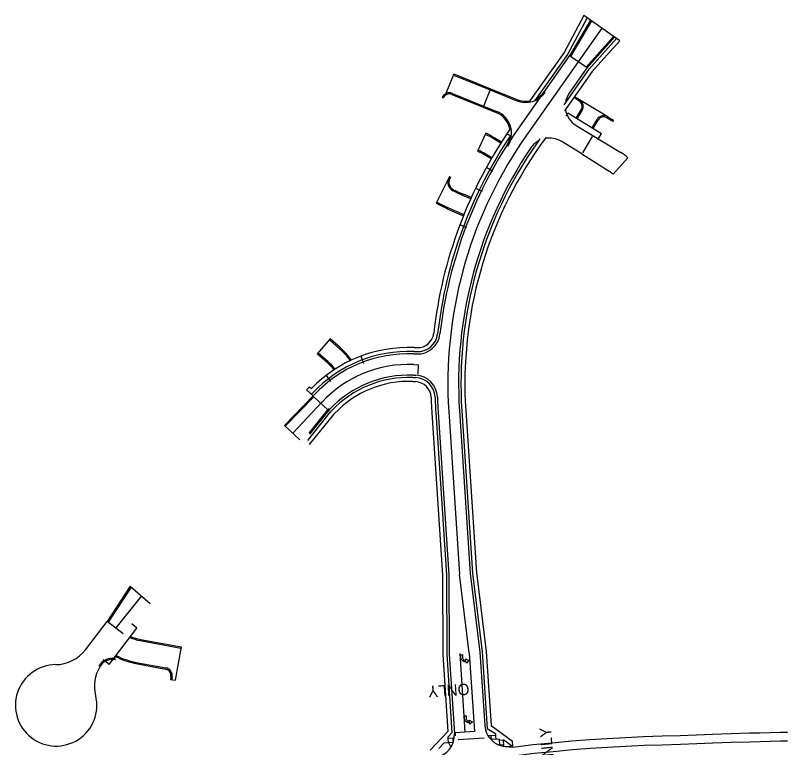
# Model space of a CAD drawing. Extents: x 979036 to 996074, y 1836928 to 1845163.
# Drawn here: x 982075 to 983051, y 1842691 to 1843617 of the extents above; entities that cross this region are included whole.
import ezdxf

# ---------------------------------------------------------------- set-up
doc = ezdxf.new("R2010")
doc.units = 0
for name, color, linetype in [('R_Proposed Road', 7, 'Continuous'), ('STRIPE_White Crosswalk', 7, 'Continuous'), ('STRIPE_White Stopbar', 7, 'Continuous'), ('STRIPE_White Turn Arrow', 7, 'Continuous'), ('STRIPE_WHITE_10_30 SKIP', 7, 'Continuous'), ('STRIPE_White_6in', 7, 'Continuous'), ('STRIPE_White_ONLY', 7, 'Continuous'), ('STRIPE_Yellow Dbl 6in', 7, 'Continuous')]:
    doc.layers.add(name, color=color, linetype=linetype)

msp = doc.modelspace()

# ---------------------------------------------------------------- linework, layer by layer
at = {"layer": 'R_Proposed Road'}
for p, q in [((982793.35, 1843617.45), (982768.45, 1843570.72)), ((982797.47, 1843614.55), (982772.72, 1843568.09)), ((982801.97, 1843611.38), (982775.24, 1843566.46)), ((982803.2, 1843610.52), (982776.53, 1843565.7)), ((982831, 1843590.94), (982796.16, 1843551.88)), ((982832.23, 1843590.08), (982797.28, 1843550.88)), ((982834.7, 1843588.34), (982799.51, 1843548.88)), ((982838.82, 1843585.44), (982803.25, 1843545.56)), ((982775.31, 1843566.56), (982709.93, 1843473.7)), ((982768.45, 1843570.72), (982724.01, 1843507.6)), ((982772.72, 1843568.09), (982731.61, 1843509.71)), ((982799.84, 1843549.29), (982768.31, 1843504.51)), ((982803.92, 1843546.41), (982768.89, 1843496.64)), ((982797.38, 1843551.02), (982774.95, 1843519.16)), ((982629.12, 1843543.47), (982618.97, 1843518.53)), ((982628.56, 1843542.08), (982674.87, 1843523.23)), ((982629.12, 1843543.47), (982675.44, 1843524.62)), ((982675.44, 1843524.62), (982666.01, 1843501.47)), ((982675.44, 1843524.62), (982709.11, 1843510.91)), ((982626.68, 1843517.47), (982666.01, 1843501.47)), ((982627.24, 1843518.86), (982666.58, 1843502.85)), ((982674.87, 1843523.23), (982708.55, 1843509.52)), ((982787.9, 1843510.82), (982781.56, 1843514.65)), ((982614.32, 1843513.64), (982615.7, 1843513.03)), ((982787.12, 1843509.53), (982780.69, 1843513.42)), ((982823.84, 1843489.09), (982787.9, 1843510.82)), ((982666.01, 1843501.47), (982682.71, 1843494.67)), ((982666.58, 1843502.85), (982683.28, 1843496.06)), ((982783.77, 1843487.56), (982790, 1843497.86)), ((982785.05, 1843486.78), (982791.28, 1843497.09)), ((982770.9, 1843490.43), (982773.07, 1843494.02)), ((982773.07, 1843494.02), (982815.86, 1843468.16)), ((982803.88, 1843475.4), (982810.11, 1843485.71)), ((982823.06, 1843487.81), (982830.17, 1843483.51)), ((982823.84, 1843489.09), (982830.95, 1843484.8)), ((982783.52, 1843478.36), (982839.97, 1843444.24)), ((982805.17, 1843474.62), (982811.39, 1843484.93)), ((982830.95, 1843484.8), (982830.17, 1843483.51)), ((982669.27, 1843468.5), (982658.86, 1843445.77)), ((982701.71, 1843464.3), (982696.1, 1843467.71)), ((982810.95, 1843460.03), (982815.86, 1843468.16)), ((982688.45, 1843455.98), (982680.16, 1843461.03)), ((982689.25, 1843457.25), (982680.94, 1843462.31)), ((982737.95, 1843461.39), (982734.46, 1843456.43)), ((982745.58, 1843463.55), (982738.55, 1843453.55)), ((982790.91, 1843442.34), (982764.6, 1843458.24)), ((982676.26, 1843435.89), (982667.94, 1843440.95)), ((982677.01, 1843437.19), (982668.72, 1843442.23)), ((982790.88, 1843442.36), (982825.46, 1843420.3)), ((982849.17, 1843437.48), (982830.63, 1843416.5)), ((982678.24, 1843420.05), (982670.11, 1843425)), ((982623.5, 1843413.67), (982606.8, 1843379.88)), ((982623.5, 1843413.67), (982624.85, 1843413.01)), ((982624.85, 1843413.01), (982623.88, 1843411.05)), ((982665.09, 1843394.57), (982656.36, 1843398.32)), ((982650.42, 1843385.63), (982640.59, 1843389.85)), ((982651.04, 1843387), (982641.18, 1843391.23)), ((982606.8, 1843379.88), (982616.11, 1843375.28)), ((982607.46, 1843381.23), (982616.78, 1843376.62)), ((982631.32, 1843368.26), (982641.18, 1843364.03)), ((982631.91, 1843369.64), (982641.74, 1843365.42)), ((982645.37, 1843348.62), (982636.63, 1843352.38)), ((982472.6, 1843208.29), (982456.1, 1843189.51)), ((982484.58, 1843195.77), (982471.61, 1843207.17)), ((982485.57, 1843196.9), (982472.6, 1843208.29)), ((982578.95, 1843197.3), (982582.34, 1843197.16)), ((982469.07, 1843178.12), (982456.1, 1843189.51)), ((982470.06, 1843179.24), (982457.09, 1843190.64)), ((982511.4, 1843186.39), (982514.75, 1843177.5)), ((982578.62, 1843189.3), (982582.02, 1843189.17)), ((982578.75, 1843192.3), (982582.14, 1843192.16)), ((982467.39, 1843161.87), (982473.18, 1843154.34)), ((982577.2, 1843154.33), (982580.59, 1843154.19)), ((982577.4, 1843159.33), (982580.79, 1843159.19)), ((982577.52, 1843162.33), (982580.92, 1843162.19)), ((982442.78, 1843143.78), (982446.6, 1843147.71)), ((982446.6, 1843147.71), (982448.94, 1843145.43)), ((982414.84, 1843098.76), (982451.09, 1843136.06)), ((982415.92, 1843097.71), (982452.16, 1843135.01)), ((982448.88, 1843138.08), (982450.34, 1843139.65)), ((982451.07, 1843136.04), (982452.53, 1843137.6)), ((982444.2, 1843079.57), (982473.21, 1843115.81)), ((982445.88, 1843088.87), (982469.69, 1843118.62)), ((982446.98, 1843087.84), (982470.87, 1843117.68)), ((982469.69, 1843118.62), (982471.16, 1843120.19)), ((982470.79, 1843117.6), (982472.25, 1843119.16)), ((982472.98, 1843115.55), (982474.45, 1843117.11)), ((982601.18, 1843114.85), (982614.59, 1842909.44)), ((982606.17, 1843115.17), (982619.59, 1842909.62)), ((982609.17, 1843115.37), (982622.59, 1842909.72)), ((982636.11, 1843117.13), (982649.53, 1842911.48)), ((982639.1, 1843117.32), (982652.52, 1842911.77)), ((982644.09, 1843117.65), (982657.5, 1842912.24)), ((982446.66, 1843074.64), (982477.11, 1843112.68)), ((982476.63, 1843112.13), (982478.1, 1843113.7)), ((982614.59, 1842909.73), (982615.12, 1842808.98)), ((982619.59, 1842909.75), (982620.12, 1842809.31)), ((982622.59, 1842909.77), (982623.12, 1842809.5)), ((982649.53, 1842911.53), (982662.04, 1842812.04)), ((982652.5, 1842911.9), (982665.04, 1842812.24)), ((982657.47, 1842912.53), (982670.04, 1842812.56)), ((982219.82, 1842895.34), (982190.77, 1842850.8)), ((982220.97, 1842894.35), (982191.96, 1842849.89)), ((982219.82, 1842895.34), (982245.08, 1842873.59)), ((982163.29, 1842815.06), (982190.77, 1842850.8)), ((982210.99, 1842835.26), (982190.77, 1842850.8)), ((982193.15, 1842796.47), (982228.22, 1842842.09)), ((982228.22, 1842842.09), (982221.99, 1842847.63)), ((982232.45, 1842826.58), (982283.98, 1842816.98)), ((982232.73, 1842828.05), (982284.25, 1842818.46)), ((982284.25, 1842818.46), (982276.43, 1842776.47)), ((982662.04, 1842812.04), (982668.1, 1842719.24)), ((982665.03, 1842812.24), (982671.35, 1842715.48)), ((982670.02, 1842812.56), (982676.13, 1842718.94)), ((982193.15, 1842796.47), (982185.62, 1842802.26)), ((982200.64, 1842802.39), (982200.92, 1842803.86)), ((982615.14, 1842808.98), (982621.5, 1842711.53)), ((982620.13, 1842809.31), (982626.63, 1842709.65)), ((982623.12, 1842809.5), (982629.69, 1842708.93)), ((982184.69, 1842798.6), (982186.81, 1842801.35)), ((982227.05, 1842797.58), (982264.5, 1842790.6)), ((982227.33, 1842799.05), (982264.78, 1842792.08)), ((982271.3, 1842780.69), (982270.72, 1842777.53)), ((982270.72, 1842777.53), (982276.43, 1842776.47)), ((982272.78, 1842780.42), (982272.19, 1842777.26)), ((982671.35, 1842715.48), (982681.61, 1842709.1)), ((982676.13, 1842718.94), (982703.09, 1842699.52)), ((982621.5, 1842711.53), (982599.06, 1842688.03)), ((982626.63, 1842709.65), (982621.86, 1842704.7)), ((982621.99, 1842702.7), (982621.86, 1842704.7)), ((982675.78, 1842706.21), (982676.11, 1842701.22)), ((982681.61, 1842709.1), (982681.77, 1842706.6)), ((982681.77, 1842706.6), (982682.1, 1842701.61)), ((982616.91, 1842697.36), (982610.13, 1842690.24)), ((982616.91, 1842697.36), (982628.3, 1842698.1)), ((982622.31, 1842697.71), (982621.99, 1842702.7)), ((982622.31, 1842697.71), (982625.37, 1842691.9)), ((982628.3, 1842698.1), (982627.98, 1842703.09)), ((982684.27, 1842701.76), (982682.1, 1842701.61)), ((982686.27, 1842701.89), (982686.76, 1842694.33)), ((982691.36, 1842700.64), (982686.32, 1842700.31)), ((982691.75, 1842694.65), (982686.76, 1842694.33)), ((982692.86, 1842700.74), (982691.36, 1842700.64)), ((982691.36, 1842700.64), (982691.86, 1842692.98)), ((982692.86, 1842700.74), (982703.33, 1842693.2)), ((982703.81, 1842693.24), (982703.09, 1842699.52)), ((982703.81, 1842693.24), (982699.73, 1842692.78)), ((982703.97, 1842691.75), (982699.9, 1842691.29))]:
    msp.add_line(p, q, dxfattribs=at)
for points in [[(982838.82, 1843585.44), (982793.35, 1843617.45)], [(982796.16, 1843551.88), (982776.53, 1843565.7)], [(982804.1, 1843464.17), (982791.69, 1843443.63)], [(982442.79, 1843143.78), (982451.07, 1843136.04)], [(982452.16, 1843135.01), (982469.69, 1843118.62)], [(982414.82, 1843098.73), (982434.18, 1843080.64)], [(982681.77, 1842706.6), (982672.37, 1842705.99)], [(982629.48, 1842703.19), (982621.99, 1842702.7)], [(982686.27, 1842701.89), (982676.11, 1842701.22)]]:
    msp.add_lwpolyline(points, dxfattribs=at)
for centre, radius, start, end in [((982623.47, 1843509.6), 10, 67.85265, 156.19028), ((982623.47, 1843509.6), 8.5, 67.85265, 156.19028), ((982719.86, 1843537.31), 30, 247.85265, 324.85265), ((982719.86, 1843537.31), 28.5, 298.3273, 324.85265), ((982798.26, 1843502.75), 28.5, 144.85265, 171.378), ((982719.86, 1843537.31), 28.5, 247.85265, 280.84922), ((982782.72, 1843502.26), 8.5, 328.85265, 58.85265), ((982782.72, 1843502.26), 10, 328.85265, 58.85265), ((982671.97, 1843468.27), 30, 327.41714, 67.85265), ((982798.26, 1843502.75), 28.5, 188.85608, 238.85265), ((982671.97, 1843468.27), 28.5, 10.44679, 67.85265), ((982818.67, 1843480.53), 10, 58.85265, 148.85265), ((982818.67, 1843480.53), 8.5, 58.85265, 148.85265), ((983167.15, 1843151.8), 567.17, 145.24329, 173.56683), ((983167.15, 1843151.8), 562.17, 145.84176, 173.56683), ((983167.15, 1843151.8), 559.17, 144.85265, 173.56683), ((982622.45, 1843366.2), 111, 58.67814, 65.40991), ((982622.45, 1843366.2), 112.5, 58.67814, 65.40991), ((983167.15, 1843151.8), 529.17, 144.85265, 183.73532), ((982671.97, 1843468.27), 28.5, 327.41714, 353.31514), ((982749.86, 1843433.85), 28.5, 118.74182, 145.94429), ((982749.86, 1843433.85), 28.5, 58.85265, 101.1144), ((983167.15, 1843151.8), 532.17, 145.94429, 183.73532), ((983167.15, 1843151.8), 524.17, 144.85265, 183.73532), ((982622.45, 1843366.2), 89, 58.67814, 65.40991), ((982622.45, 1843366.2), 87.5, 58.67814, 65.40991), ((982807.13, 1843389.9), 63.5, 48.53941, 58.85265), ((982807.13, 1843389.9), 35.5, 48.53941, 58.85265), ((982633.29, 1843406.39), 12, 153.6922, 244.02443), ((982633.29, 1843406.39), 10.5, 153.6922, 244.02443), ((982754.61, 1843655.41), 289, 244.02443, 246.76304), ((982754.61, 1843655.41), 287.5, 244.02443, 246.76304), ((982754.61, 1843655.41), 312.5, 243.6922, 246.76304), ((982754.61, 1843655.41), 311, 243.6922, 246.76304), ((982583.18, 1843217.64), 28.5, 267.66515, 353.56683), ((982583.18, 1843217.64), 25.5, 267.66515, 353.56683), ((982583.18, 1843217.64), 20.5, 267.66515, 353.56683), ((982571.96, 1843025.94), 171.5, 87.66515, 135.83424), ((982424.53, 1843127.4), 91, 35.91844, 48.7117), ((982424.53, 1843127.4), 92.5, 35.74275, 48.7117), ((982571.96, 1843025.94), 166.5, 87.66515, 136.92515), ((982571.96, 1843025.94), 163.5, 87.66515, 136.92515), ((982424.53, 1843127.4), 67.5, 38.19444, 48.7117), ((982424.53, 1843127.4), 69, 38.08422, 48.7117), ((982571.96, 1843025.94), 136.5, 87.66515, 136.92515), ((982571.96, 1843025.94), 133.5, 87.66515, 136.92515), ((982571.96, 1843025.94), 128.5, 87.66515, 136.92515), ((982579.76, 1843133.71), 20.5, 1.76347, 87.66515), ((982579.76, 1843133.71), 25.5, 1.76347, 87.66515), ((982579.76, 1843133.71), 28.5, 1.76347, 87.66515), ((983167.15, 1843151.8), 567.17, 181.76347, 183.73532), ((983167.15, 1843151.8), 562.17, 181.76347, 183.73532), ((983167.15, 1843151.8), 559.17, 181.76347, 183.73532), ((982244.54, 1842891.46), 64.5, 247.87466, 259.4497), ((982244.54, 1842891.46), 66, 247.51555, 259.4497), ((982124.84, 1842844.62), 48.5, 270.7606, 322.44446), ((982197.26, 1842784.2), 20, 79.4497, 149.64322), ((982197.26, 1842784.2), 18.5, 79.4497, 149.64322), ((982244.54, 1842891.46), 95.5, 242.79662, 259.4497), ((982244.54, 1842891.46), 94, 242.96368, 259.4497), ((982126.17, 1842744.63), 51.5, 90.7606, 14.12833), ((982223.14, 1842769.04), 48.5, 149.64322, 194.12833), ((982223.14, 1842769.04), 48.5, 142.44446, 149.64322), ((982262.95, 1842782.25), 8.5, 349.4497, 79.4497), ((982262.95, 1842782.25), 10, 349.4497, 79.4497), ((982696.54, 1842721.1), 28.5, 183.73532, 276.43492), ((982601.25, 1842707.07), 28.5, 279.12753, 3.73532)]:
    msp.add_arc(centre, radius, start, end, dxfattribs=at)
at = {"layer": 'STRIPE_White Crosswalk'}
msp.add_lwpolyline([(982667.21, 1842703.15), (982634.3, 1842701)], dxfattribs=at)
at = {"layer": 'STRIPE_White Stopbar'}
msp.add_line((982583.98, 1843163.56), (982584.46, 1843175.55), dxfattribs=at)
msp.add_lwpolyline([(982655.08, 1842711.37), (982631.13, 1842709.81)], dxfattribs=at)
at = {"layer": 'STRIPE_White Turn Arrow'}
for points in [[(982644.04, 1842803.28), (982647.88, 1842801.21), (982644.89, 1842798.03), (982644.62, 1842799.67), (982643.96, 1842799.62), (982643.38, 1842799.62), (982642.57, 1842799.74), (982641.61, 1842800.04), (982640.85, 1842800.41), (982640.22, 1842800.92), (982639.49, 1842801.5), (982639.05, 1842802.16), (982638.57, 1842802.87), (982638.24, 1842803.8), (982638.03, 1842804.77), (982637.84, 1842808.66), (982639.84, 1842808.77), (982640.05, 1842805.18), (982640.14, 1842804.49), (982640.41, 1842803.78), (982640.83, 1842803.02), (982641.44, 1842802.42), (982641.76, 1842802.22), (982642.4, 1842801.89), (982643.17, 1842801.69), (982643.91, 1842801.63), (982644.3, 1842801.64)], [(982648.59, 1842726.06), (982652.43, 1842723.98), (982649.45, 1842720.8), (982649.18, 1842722.44), (982648.52, 1842722.4), (982647.94, 1842722.4), (982647.13, 1842722.51), (982646.17, 1842722.81), (982645.41, 1842723.18), (982644.78, 1842723.69), (982644.05, 1842724.27), (982643.61, 1842724.93), (982643.13, 1842725.65), (982642.8, 1842726.57), (982642.58, 1842727.54), (982642.39, 1842731.44), (982644.4, 1842731.54), (982644.6, 1842727.95), (982644.7, 1842727.27), (982644.96, 1842726.55), (982645.39, 1842725.79), (982646, 1842725.19), (982646.31, 1842724.99), (982646.95, 1842724.66), (982647.73, 1842724.46), (982648.47, 1842724.4), (982648.86, 1842724.41)]]:
    msp.add_lwpolyline(points, close=True, dxfattribs=at)
at = {"layer": 'STRIPE_WHITE_10_30 SKIP'}
msp.add_lwpolyline([(982699.15, 1842680.13), (982708.42, 1842681.27), (982730.47, 1842683.98), (982754.66, 1842686.43), (982778.95, 1842688.89), (982801.31, 1842690.28), (982823.49, 1842691.67), (982846.45, 1842692.89), (982869.48, 1842694.11), (982892.65, 1842694.89), (982915.7, 1842695.67), (982936.09, 1842696.4), (982956.5, 1842697.12), (982979.85, 1842697.89), (983003.22, 1842698.65), (983016.23, 1842698.98), (983029.19, 1842699.31), (983042.16, 1842699.64), (983051, 1842699.86)], dxfattribs=at)
at = {"layer": 'STRIPE_White_6in'}
msp.add_line((982636.59, 1842810.38), (982643.11, 1842710.59), dxfattribs=at)
msp.add_lwpolyline([(982703.97, 1842691.8), (982707.07, 1842692.18), (982729.25, 1842694.92), (982753.55, 1842697.38), (982778.05, 1842699.86), (982800.62, 1842701.26), (982822.86, 1842702.65), (982845.87, 1842703.87), (982869, 1842705.1), (982892.28, 1842705.89), (982915.32, 1842706.67), (982935.7, 1842707.39), (982956.13, 1842708.11), (982979.49, 1842708.88), (983002.9, 1842709.65), (983015.95, 1842709.98), (983028.92, 1842710.31), (983041.88, 1842710.63), (983050.72, 1842710.86)], dxfattribs=at)
msp.add_arc((982601.25, 1842707.07), 30, 358.10738, 3.73532, dxfattribs=at)
at = {"layer": 'STRIPE_Yellow Dbl 6in'}
for p, q in [((982816.28, 1843601.31), (982786.34, 1843558.79)), ((982786.34, 1843558.79), (982715.06, 1843457.37)), ((982578.07, 1843175.81), (982584.46, 1843175.55)), ((982425.42, 1843088.83), (982462.61, 1843128.62)), ((982622.64, 1843116.25), (982636.07, 1842910.56)), ((982648.57, 1842811.16), (982636.07, 1842910.56)), ((982233.86, 1842883.25), (982201.48, 1842842.58)), ((982648.57, 1842811.16), (982655.08, 1842711.37))]:
    msp.add_line(p, q, dxfattribs=at)
for centre, radius, start, end in [((983167.15, 1843151.8), 545.67, 145.94429, 183.73532), ((982571.96, 1843025.94), 150, 87.66515, 136.92515)]:
    msp.add_arc(centre, radius, start, end, dxfattribs=at)

# ---------------------------------------------------------------- texts
at = {"layer": 'STRIPE_White_ONLY'}
for rotation, p in [(183.73532, (982648.23, 1842772.37)), (95.70664, (982756.73, 1842665.28))]:
    msp.add_text('ONLY', height=14.4, rotation=rotation, dxfattribs=at).set_placement(p)

doc.saveas('drawing.dxf')
